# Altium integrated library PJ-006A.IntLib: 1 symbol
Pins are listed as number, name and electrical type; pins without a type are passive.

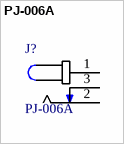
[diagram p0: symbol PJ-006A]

## PJ-006A
designator J?
2.0 x 6.3 mm, 2.0 A, Vertical, Through Hole, Dc Power Jack Connector; MF: Same Sky
footprint *CUI_PJ-006A
pins: 1, 2, 3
